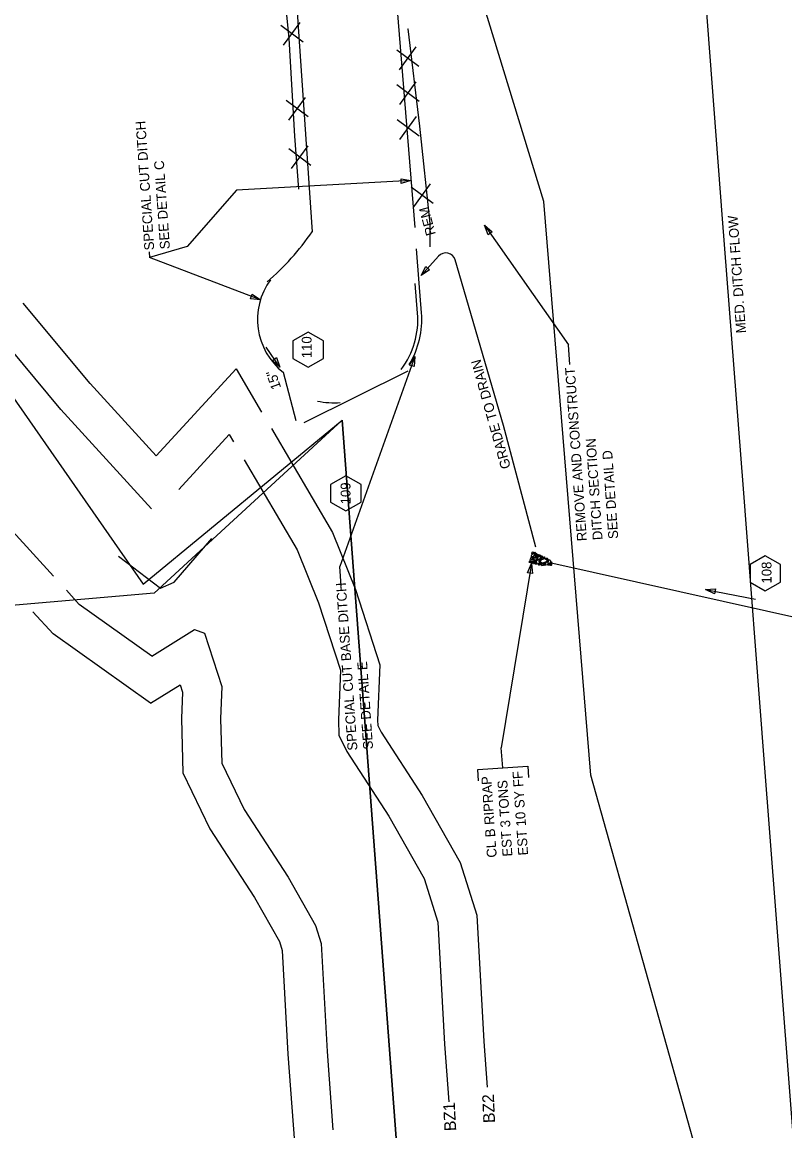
# Model space of a CAD drawing. Extents: x 2384780 to 2405432, y 547869 to 573706.
# Drawn here: x 2399968 to 2400357, y 565211 to 565776 of the extents above; entities that cross this region are included whole.
import ezdxf

# ---------------------------------------------------------------- set-up
doc = ezdxf.new("R2010")
doc.units = 0
for name, color, linetype in [('Old_Level_1', 7, 'Continuous'), ('Old_Level_18', 7, 'Continuous'), ('Old_Level_19', 7, 'Continuous'), ('Old_Level_20', 7, 'Continuous'), ('Old_Level_5', 7, 'Continuous'), ('Old_Level_6', 7, 'Continuous'), ('Old_Level_62', 7, 'Continuous'), ('Old_Level_63', 7, 'Continuous'), ('Prop Buffer Zone 1', 7, 'Continuous'), ('Prop Buffer Zone 2', 7, 'Continuous'), ('Prop Drainage Box Number Symbol CELL', 7, 'Continuous')]:
    doc.layers.add(name, color=color, linetype=linetype)

msp = doc.modelspace()

# ---------------------------------------------------------------- linework, layer by layer
at = {"layer": 'Old_Level_1'}
for p, q in [((2400107.83, 565572.84), (2400101.29, 565597.47)), ((2400164.68, 565598.14), (2400111.74, 565571.85)), ((2400425.62, 565458.39), (2400237.14, 565500.51))]:
    msp.add_line(p, q, dxfattribs=at)
for points in [[(2400229.15, 565505.11), (2400229.09, 565504.59), (2400228.87, 565503.64), (2400228.1, 565503.49), (2400227.69, 565503.83), (2400228.07, 565504.97), (2400228.64, 565505.24), (2400229.15, 565505.11)], [(2400228.62, 565505.95), (2400228.62, 565505.64), (2400228.54, 565505.16), (2400228.18, 565505.14), (2400227.95, 565505.27), (2400228.18, 565505.87), (2400228.45, 565506.03), (2400228.62, 565505.95)], [(2400229.63, 565505.83), (2400229.63, 565505.52), (2400229.54, 565505.04), (2400229.19, 565505.02), (2400228.95, 565505.15), (2400229.19, 565505.75), (2400229.45, 565505.91), (2400229.63, 565505.83)], [(2400229.08, 565503.11), (2400229, 565503.49), (2400229.06, 565504.21), (2400229.43, 565504.42), (2400229.72, 565504.34), (2400229.72, 565503.49), (2400229.53, 565503.16), (2400229.08, 565503.11)], [(2400230.13, 565505.36), (2400230.14, 565505.05), (2400230.06, 565504.56), (2400229.7, 565504.55), (2400229.47, 565504.68), (2400229.7, 565505.28), (2400229.97, 565505.44), (2400230.13, 565505.36)], [(2400230.14, 565504.77), (2400230.45, 565504.89), (2400230.96, 565504.9), (2400231.08, 565504.64), (2400231.03, 565504.47), (2400230.39, 565504.39), (2400230.2, 565504.56), (2400230.14, 565504.77)], [(2400230.93, 565503.63), (2400230.92, 565503.85), (2400230.95, 565504.35), (2400231.21, 565504.51), (2400231.36, 565504.48), (2400231.45, 565503.94), (2400231.26, 565503.69), (2400231.05, 565503.63)], [(2400231.47, 565504.4), (2400231.7, 565504.56), (2400232.2, 565504.55), (2400232.35, 565504.27), (2400232.3, 565504.09), (2400231.67, 565504.03), (2400231.49, 565504.2), (2400231.47, 565504.4)], [(2400226.56, 565500.96), (2400226.79, 565501.14), (2400227.29, 565501.12), (2400227.46, 565500.85), (2400227.37, 565500.68), (2400226.79, 565500.63), (2400226.63, 565500.75), (2400226.56, 565500.96)], [(2400228.86, 565501.2), (2400228.39, 565501.01), (2400227.36, 565500.97), (2400226.98, 565501.57), (2400227.23, 565502.05), (2400228.47, 565502.04), (2400228.85, 565501.74), (2400228.93, 565501.18)], [(2400228.26, 565503.32), (2400228.23, 565502.95), (2400228.07, 565502.34), (2400227.51, 565502.28), (2400227.25, 565502.43), (2400227.59, 565503.31), (2400227.95, 565503.45), (2400228.26, 565503.32)], [(2400228.36, 565500.95), (2400228.39, 565500.64), (2400228.18, 565500.27), (2400227.8, 565500.18), (2400227.65, 565500.34), (2400227.81, 565500.92), (2400228.18, 565501.01), (2400228.36, 565500.95)], [(2400228.04, 565502.46), (2400228.28, 565502.63), (2400228.79, 565502.63), (2400228.94, 565502.35), (2400228.89, 565502.17), (2400228.25, 565502.1), (2400228.06, 565502.26), (2400228.04, 565502.46)], [(2400228.85, 565499.99), (2400228.71, 565500.31), (2400228.75, 565500.75), (2400228.99, 565500.97), (2400229.28, 565500.9), (2400229.2, 565500.3), (2400229.06, 565500.03), (2400228.85, 565499.99)], [(2400230.65, 565502), (2400230.21, 565501.93), (2400229.15, 565501.9), (2400228.81, 565502.49), (2400228.95, 565503), (2400230.17, 565502.95), (2400230.72, 565502.65), (2400230.65, 565502.12)], [(2400229.32, 565501.58), (2400229.53, 565501.71), (2400230.09, 565501.73), (2400230.25, 565501.45), (2400230.16, 565501.29), (2400229.53, 565501.22), (2400229.37, 565501.33), (2400229.32, 565501.58)], [(2400230.14, 565501.12), (2400230.18, 565500.8), (2400229.97, 565500.43), (2400229.59, 565500.33), (2400229.44, 565500.49), (2400229.59, 565501.07), (2400229.96, 565501.17), (2400230.14, 565501.12)], [(2400229.53, 565500.13), (2400229.76, 565500.31), (2400230.26, 565500.28), (2400230.44, 565500.02), (2400230.35, 565499.85), (2400229.76, 565499.8), (2400229.6, 565499.91), (2400229.53, 565500.13)], [(2400229.92, 565504.1), (2400230.12, 565504.12), (2400230.65, 565504.19), (2400230.8, 565503.83), (2400230.75, 565503.65), (2400230.07, 565503.6), (2400229.97, 565503.85), (2400229.92, 565504.1)], [(2400230.04, 565503.33), (2400230.31, 565503.5), (2400230.81, 565503.48), (2400230.97, 565503.2), (2400230.89, 565503.03), (2400230.3, 565502.99), (2400230.1, 565503.12), (2400230.04, 565503.33)], [(2400230.59, 565499.98), (2400230.46, 565500.5), (2400230.3, 565501.67), (2400231.15, 565502.11), (2400231.62, 565501.99), (2400231.67, 565500.5), (2400231.21, 565499.89), (2400230.57, 565499.85)], [(2400232.33, 565503.78), (2400232.29, 565503.25), (2400231.94, 565502.3), (2400231.28, 565502.16), (2400230.82, 565502.46), (2400231.22, 565503.59), (2400231.84, 565503.98), (2400232.33, 565503.78)], [(2400231.5, 565499.3), (2400231.37, 565499.53), (2400231.37, 565499.96), (2400231.63, 565500.2), (2400231.95, 565500.12), (2400231.87, 565499.52), (2400231.69, 565499.26), (2400231.5, 565499.3)], [(2400232.31, 565501.86), (2400232.35, 565501.54), (2400232.14, 565501.17), (2400231.76, 565501.07), (2400231.61, 565501.23), (2400231.77, 565501.81), (2400232.13, 565501.92), (2400232.31, 565501.86)], [(2400231.83, 565500.53), (2400232.07, 565500.68), (2400232.55, 565500.63), (2400232.72, 565500.38), (2400232.66, 565500.17), (2400232.04, 565500.16), (2400231.89, 565500.32), (2400231.83, 565500.53)], [(2400231.91, 565499.72), (2400232.15, 565499.88), (2400232.65, 565499.86), (2400232.81, 565499.6), (2400232.72, 565499.43), (2400232.14, 565499.38), (2400231.98, 565499.5), (2400231.91, 565499.72)], [(2400232.14, 565502.43), (2400232.36, 565502.61), (2400232.86, 565502.55), (2400233.03, 565502.32), (2400232.97, 565502.11), (2400232.35, 565502.06), (2400232.16, 565502.23), (2400232.14, 565502.43)], [(2400232.37, 565501.56), (2400233.02, 565502.12), (2400234.65, 565502.74), (2400235.57, 565501.96), (2400235.59, 565501.14), (2400233.6, 565500.3), (2400232.69, 565500.67), (2400232.22, 565501.49)], [(2400232.48, 565502.71), (2400232.43, 565502.95), (2400232.36, 565503.48), (2400232.73, 565503.58), (2400232.88, 565503.54), (2400232.95, 565502.89), (2400232.8, 565502.74), (2400232.48, 565502.71)], [(2400232.4, 565503.93), (2400232.63, 565504.1), (2400233.13, 565504.09), (2400233.29, 565503.81), (2400233.24, 565503.63), (2400232.61, 565503.56), (2400232.42, 565503.73), (2400232.4, 565503.93)], [(2400233.8, 565500.09), (2400233.81, 565499.67), (2400233.65, 565499.09), (2400233.1, 565499), (2400232.84, 565499.23), (2400233.15, 565500.04), (2400233.52, 565500.17), (2400233.8, 565500.09)], [(2400233.61, 565503.59), (2400233.75, 565503.25), (2400233.77, 565502.54), (2400233.39, 565502.3), (2400233.1, 565502.38), (2400233.01, 565503.25), (2400233.3, 565503.57), (2400233.61, 565503.59)], [(2400234.48, 565503.47), (2400234.48, 565503.16), (2400234.39, 565502.67), (2400234.04, 565502.66), (2400233.8, 565502.79), (2400234.04, 565503.39), (2400234.3, 565503.54), (2400234.48, 565503.47)], [(2400233.8, 565499.52), (2400234.03, 565499.7), (2400234.53, 565499.67), (2400234.7, 565499.4), (2400234.62, 565499.23), (2400234.02, 565499.19), (2400233.86, 565499.3), (2400233.8, 565499.52)], [(2400233.83, 565500.11), (2400234.11, 565500.26), (2400234.58, 565500.2), (2400234.76, 565499.97), (2400234.7, 565499.75), (2400234.03, 565499.73), (2400233.88, 565499.89), (2400233.83, 565500.11)], [(2400234.22, 565500.55), (2400234.45, 565500.72), (2400234.94, 565500.7), (2400235.12, 565500.44), (2400235.03, 565500.27), (2400234.43, 565500.22), (2400234.27, 565500.34), (2400234.22, 565500.55)], [(2400236.16, 565500.96), (2400236.15, 565500.46), (2400235.9, 565499.47), (2400235.15, 565499.31), (2400234.8, 565499.61), (2400235.19, 565500.78), (2400235.7, 565501.07), (2400236.16, 565500.96)], [(2400234.92, 565502.73), (2400235.19, 565502.86), (2400235.69, 565502.85), (2400235.86, 565502.61), (2400235.79, 565502.39), (2400235.14, 565502.37), (2400234.97, 565502.52), (2400234.92, 565502.73)], [(2400235.46, 565502.25), (2400235.69, 565502.42), (2400236.19, 565502.41), (2400236.34, 565502.13), (2400236.29, 565501.95), (2400235.66, 565501.89), (2400235.48, 565502.05), (2400235.46, 565502.25)], [(2400236.39, 565501.83), (2400236.34, 565501.61), (2400236.23, 565501.17), (2400235.9, 565501.14), (2400235.72, 565501.19), (2400235.88, 565501.77), (2400236.16, 565502), (2400236.39, 565501.83)], [(2400236.04, 565499.88), (2400236.38, 565499.97), (2400237.01, 565500.04), (2400237.32, 565499.6), (2400237.22, 565499.21), (2400236.3, 565499.26), (2400236.06, 565499.52), (2400236.04, 565499.88)], [(2400237.35, 565501.92), (2400237.42, 565501.48), (2400237.46, 565500.46), (2400236.86, 565500.07), (2400236.35, 565500.25), (2400236.38, 565501.48), (2400236.81, 565501.96), (2400237.23, 565501.95)], [(2400237.5, 565499.13), (2400237.48, 565499.37), (2400237.39, 565499.94), (2400237.72, 565500), (2400237.91, 565499.97), (2400237.99, 565499.36), (2400237.79, 565499.06), (2400237.5, 565499.13)], [(2400237.64, 565500.15), (2400237.62, 565500.37), (2400237.53, 565500.91), (2400237.86, 565501.02), (2400238.04, 565500.97), (2400238.15, 565500.31), (2400237.92, 565500.06), (2400237.64, 565500.15)]]:
    msp.add_lwpolyline(points, dxfattribs=at)
at = {"layer": 'Old_Level_18'}
for p, q in [((2400156.01, 565822.12), (2400168.29, 565671.35)), ((2400105.85, 565817.95), (2400115.98, 565669.27)), ((2400169.72, 565627.76), (2400168.51, 565642.89)), ((2400171.71, 565627.92), (2400170.5, 565643.05))]:
    msp.add_line(p, q, dxfattribs=at)
for centre, radius, start, end in [((2400006.02, 565744.75), 133.37, 310.7161, 325.5321), ((2400122.51, 565624.53), 34.39, 143.8563, 231.8917), ((2400127.37, 565624.52), 42.47, 323.2389, 4.4041), ((2400127.37, 565624.52), 44.47, 329.0458, 4.4041), ((2400127.37, 565624.52), 42.47, 258.2009, 273.9698)]:
    msp.add_arc(centre, radius, start, end, dxfattribs=at)
at = {"layer": 'Old_Level_19'}
msp.add_lwpolyline([(2400316.39, 565787.76), (2400325.01, 565675.82), (2400335.45, 565540.33), (2400346.22, 565400.39), (2400358.59, 565239.79), (2400367.12, 565129.03)], dxfattribs=at)
at = {"layer": 'Old_Level_20'}
msp.add_lwpolyline([(2400200.75, 565389.35), (2400200.35, 565395.1), (2400225.84, 565396.88), (2400226.25, 565391.13)], dxfattribs=at)
at = {"layer": 'Old_Level_5'}
for p, q in [((2400166.33, 565695.31), (2400077.33, 565690.4)), ((2400077.33, 565690.4), (2400052.21, 565661.73)), ((2400203.83, 565672.53), (2400246.56, 565611.6)), ((2400032.84, 565659.02), (2400033.04, 565656.08)), ((2400052.21, 565661.73), (2400033.04, 565656.08)), ((2400171.55, 565646.96), (2400180.35, 565656.8)), ((2400089.6, 565634.52), (2400033.04, 565656.08)), ((2400247.25, 565601.62), (2400246.56, 565611.6)), ((2400099.53, 565600.24), (2400092.6, 565610.36)), ((2400168.39, 565605.63), (2400130.02, 565498.66)), ((2400130.72, 565488.69), (2400130.02, 565498.66)), ((2400227.8, 565500.18), (2400212.38, 565406.24)), ((2400316.43, 565486.87), (2400341.96, 565481.98)), ((2400213.1, 565395.99), (2400212.38, 565406.24))]:
    msp.add_line(p, q, dxfattribs=at)
for points in [[(2400161.27, 565696.28), (2400166.33, 565695.31), (2400161.41, 565693.78)], [(2400205.69, 565667.73), (2400203.83, 565672.53), (2400207.74, 565669.17)], [(2400175.81, 565649.85), (2400171.55, 565646.96), (2400173.95, 565651.52)], [(2400085.38, 565637.47), (2400089.6, 565634.52), (2400084.49, 565635.13)], [(2400097.74, 565605.07), (2400099.53, 565600.24), (2400095.68, 565603.66)], [(2400165.63, 565601.28), (2400168.39, 565605.63), (2400168, 565600.49)], [(2400225.76, 565495.45), (2400227.8, 565500.18), (2400228.23, 565495.04)], [(2400321.11, 565484.7), (2400316.43, 565486.87), (2400321.58, 565487.16)]]:
    msp.add_lwpolyline(points, close=True, dxfattribs=at)
msp.add_lwpolyline([(2400229.99, 565508.46), (2400213.49, 565570.55), (2400188.88, 565654.87)], dxfattribs=at)
msp.add_arc((2400184.08, 565653.46), 5, 16.2733, 138.1665, dxfattribs=at)
at = {"layer": 'Old_Level_6'}
msp.add_lwpolyline([(2400017.3, 565503.88), (2400038.59, 565487.51), (2400045.68, 565490.56), (2400064.9, 565512.95)], dxfattribs=at)
at = {"layer": 'Old_Level_62'}
for points in [[(2400339.33, 564522.76), (2400485.81, 564616.68), (2400370.09, 564992.65), (2400258.07, 565392.28), (2400234.01, 565684.68), (2400121.91, 566051.12), (2399969.11, 566416.3), (2399876.99, 566204.34), (2399744.83, 566140.38), (2399726.75, 565925.09), (2400029.82, 565489.59), (2400131.32, 565573.2), (2400194.24, 564735.04)], [(2399585.74, 565446.07), (2399318.45, 564609.59), (2399554.05, 564046.03), (2400148.02, 564421.39), (2400339.33, 564522.76), (2400194.24, 564735.04), (2400131.32, 565573.2), (2400035.5, 565485.1)]]:
    msp.add_lwpolyline(points, close=True, dxfattribs=at)
at = {"layer": 'Old_Level_63'}
for p, q in [((2400101.45, 565764.31), (2400109.89, 565775.9)), ((2400111.31, 565765.88), (2400100.04, 565774.33)), ((2400170.39, 565753.41), (2400159.13, 565761.86)), ((2400160.54, 565751.84), (2400168.98, 565763.43)), ((2400170.45, 565735.7), (2400159.19, 565744.15)), ((2400160.6, 565734.13), (2400169.04, 565745.72)), ((2400114, 565727.74), (2400102.73, 565736.2)), ((2400104.14, 565726.17), (2400112.58, 565737.76)), ((2400170.51, 565717.91), (2400159.25, 565726.36)), ((2400160.66, 565716.34), (2400169.1, 565727.93)), ((2400115.33, 565703.01), (2400104.07, 565711.46)), ((2400105.48, 565701.44), (2400113.92, 565713.03)), ((2400177.64, 565683.6), (2400166.38, 565692.05)), ((2400167.79, 565682.03), (2400176.23, 565693.62)), ((2400170.5, 565643.05), (2400169.1, 565660.53))]:
    msp.add_line(p, q, dxfattribs=at)
for points in [[(2400109.17, 565690.88), (2400107.07, 565717.9), (2400104.25, 565767.82), (2400099.93, 565810.9), (2400097.6, 565866.92)], [(2400176.08, 565661.54), (2400176.1, 565673.38), (2400170.81, 565723.1), (2400164.9, 565772.66), (2400164.71, 565772.27)]]:
    msp.add_lwpolyline(points, dxfattribs=at)
at = {"layer": 'Prop Buffer Zone 1'}
for p, q in [((2400048.02, 565537.93), (2400073.71, 565565.95)), ((2400073.71, 565565.95), (2400075.92, 565562.19)), ((2400081.37, 565552.91), (2400108.31, 565507.06))]:
    msp.add_line(p, q, dxfattribs=at)
for points in [[(2400034.08, 565527.97), (2399987.8, 565578.71), (2399955.39, 565617.54)], [(2399984.15, 565493.68), (2399942.59, 565539.24), (2399918.93, 565567.58)], [(2400108.31, 565507.06), (2400119.2, 565480.1), (2400130.38, 565445.72), (2400129.35, 565420.49), (2400129.54, 565412.71), (2400133.62, 565404.26), (2400155.01, 565371.43), (2400173.04, 565339.66), (2400180.11, 565317.29), (2400183.43, 565255.2), (2400185.64, 565225.67)], [(2399997.28, 565479.29), (2399990.7, 565486.49)], [(2400034.26, 565452.98), (2399997.28, 565479.29)], [(2400034.26, 565452.98), (2400055.97, 565466.44), (2400061.16, 565464.56)], [(2400061.16, 565464.56), (2400070, 565437.41), (2400069.32, 565420.98), (2400069.88, 565398.31), (2400081.25, 565374.73), (2400103.74, 565340.22), (2400117.74, 565315.55), (2400120.61, 565306.48), (2400123.55, 565251.36), (2400126.54, 565211.48)]]:
    msp.add_lwpolyline(points, dxfattribs=at)
at = {"layer": 'Prop Buffer Zone 2'}
for p, q in [((2400036.51, 565554.98), (2400077.26, 565599.4)), ((2400077.26, 565599.4), (2400090.24, 565577.3)), ((2400095.17, 565568.92), (2400126.3, 565515.92))]:
    msp.add_line(p, q, dxfattribs=at)
for points in [[(2400036.51, 565554.98), (2400002.87, 565591.86), (2399968.67, 565632.83)], [(2400126.3, 565515.92), (2400138, 565486.95), (2400150.51, 565448.49), (2400149.36, 565420.33), (2400149.43, 565417.52), (2400151.08, 565414.1), (2400172.1, 565381.84), (2400191.48, 565347.7), (2400199.95, 565320.89), (2400203.4, 565256.48), (2400205.13, 565233.2)], [(2399983.94, 565464.23), (2399973.6, 565475.57)], [(2400033.5, 565428.98), (2399983.94, 565464.23)], [(2400033.5, 565428.98), (2400048.65, 565438.37)], [(2400048.65, 565438.37), (2400049.87, 565434.63), (2400049.31, 565421.14), (2400049.99, 565393.5), (2400063.79, 565364.88), (2400086.65, 565329.82), (2400099.3, 565307.51), (2400100.77, 565302.87), (2400103.59, 565250.08), (2400106.97, 565204.94)]]:
    msp.add_lwpolyline(points, dxfattribs=at)
at = {"layer": 'Prop Drainage Box Number Symbol CELL'}
for points in [[(2400113.94, 565600.15), (2400121.69, 565604.63), (2400121.69, 565613.58), (2400113.94, 565618.05), (2400106.19, 565613.58), (2400106.19, 565604.63)], [(2400133.14, 565526.97), (2400140.89, 565531.45), (2400140.89, 565540.4), (2400133.14, 565544.87), (2400125.39, 565540.4), (2400125.39, 565531.45)], [(2400346.94, 565486.15), (2400354.69, 565490.62), (2400354.69, 565499.57), (2400346.94, 565504.05), (2400339.19, 565499.57), (2400339.19, 565490.62)]]:
    msp.add_lwpolyline(points, close=True, dxfattribs=at)

# ---------------------------------------------------------------- texts
at = {"layer": 'Old_Level_19'}
msp.add_text('MED. DITCH FLOW', height=5, rotation=94.13, dxfattribs=at).set_placement((2400337.15, 565617.67))
at = {"layer": 'Old_Level_5'}
for s, rotation, p in [('SPECIAL CUT DITCH', 93.9999, (2400035.52, 565659.95)), ('SEE DETAIL C', 93.9999, (2400043.5, 565660.51)), ('REM', 105.1651, (2400179.06, 565668.04)), ('GRADE TO DRAIN', 105.6842, (2400217.28, 565549.16)), ('15" ', 108.6858, (2400100.21, 565589.8)), ('REMOVE AND CONSTRUCT', 93.9999, (2400256.05, 565511.69)), ('DITCH SECTION', 93.9999, (2400264.03, 565512.25)), ('SEE DETAIL D', 93.9999, (2400272.01, 565512.81)), ('SPECIAL CUT BASE DITCH', 93.9999, (2400139.08, 565404.97)), ('SEE DETAIL E', 93.9999, (2400147.06, 565405.52)), ('CL B RIPRAP', 93.9999, (2400210.1, 565350.39)), ('EST 10 SY FF', 93.9999, (2400226.06, 565351.51)), ('EST 3 TONS', 93.9999, (2400218.08, 565350.95))]:
    msp.add_text(s, height=5, rotation=rotation, dxfattribs=at).set_placement(p)
at = {"layer": 'Prop Buffer Zone 1'}
msp.add_text('BZ1', height=6, rotation=93.0566, dxfattribs=at).set_placement((2400189.44, 565210.96))
at = {"layer": 'Prop Buffer Zone 2'}
msp.add_text('BZ2', height=6, rotation=92.4969, dxfattribs=at).set_placement((2400209.24, 565215.05))
at = {"layer": 'Prop Drainage Box Number Symbol CELL'}
for s, p in [('110', (2400115.72, 565604.81)), ('109', (2400135.54, 565530.32)), ('108', (2400350.14, 565489.95))]:
    msp.add_text(s, height=5, rotation=90.3224, dxfattribs=at).set_placement(p)

doc.saveas('drawing.dxf')
